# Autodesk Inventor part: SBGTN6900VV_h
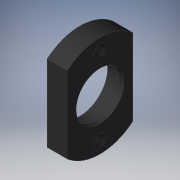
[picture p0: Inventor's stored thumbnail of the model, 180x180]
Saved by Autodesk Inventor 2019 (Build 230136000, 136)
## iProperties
Created: 2022-11
Part Number: SBGTN6900VV_h
Material: Generic
Catalog Web Link: www.cadenas.de
Description: BGTNB, BGTN, SBGTN_housing-Bearings with Housings - Space Saving, Small Flange - Non-Retained
Vendor: MISUMI
Document SubType Name: Modeling
Designer: psAdmin
Manufacturer: MISUMI
Mass: 4.62204 g
Surface Area: 29.706 cm^2
Volume: 4.62204 cm^3
Density: 1 g/cm^3
Appearance: PSOLRGB-175-175-175
Category: PARTsolutions
Company: MISUMI
Title: SBGTN6900VV
Author: Cadenas PARTsolutions
Comments: Bearings with Housings - Space Saving, Small Flange - Non-Retained
PSOL_IDENT_0: {$CADENAS_DATA/23d-libs/misumi/metric/12_bearing_holders/bgtnb/housing_bgtnb.prj},201 {VTYP=3D},{NB=
PSOL_IDENT_1: SBGTN6900VV_h},{LINA=SBGTN6900VV},{NN=BGTNB, BGTN, SBGTN_housing},{DATE=25.04.2017 02:57:07},{GEOMDA
PSOL_IDENT_2: TE=10.07.2015 02:20:10},{VERSION=},{LINEID=90},{WBVAR=MATB,ST,SEAL,ALT1},{WBNUMERIC=}  {NB=SBGTN6900
PSOL_IDENT_3: VV_h},{LINA=SBGTN6900VV},{KT=DUMMY},{PN=SBGTN6900VV},{TYPE=SBGTN},{MATB=SS},{MATBALG= 'S' , 'Steel'
PSOL_IDENT_4: , 'SS' , 'Stainless Steel' },{ST=-},{STALG= '-' , '-' },{BN=6900},{SEAL=VV},{SEALALG= 'ZZ' , 'Double
PSOL_IDENT_5: Shielded' , 'VV' , 'Non-Contact Sealed Rubber Seal' , 'DD' , 'Contact Sealed Rubber Seal' },{DD=10}
PSOL_IDENT_6: ,{D=22},{B=6},{H=40},{W=26},{T=8},{DDHH=19},{A=31},{F=0},{M=M5},{ALT1=},{M3D=5}
NB: SBGTN6900VV_h
NN: BGTNB, BGTN, SBGTN_housing
NT: Bearings with Housings - Space Saving, Small Flange - Non-Retained
NBSYN: $PN._h
LINA: SBGTN6900VV
CATALOG: Misumi
PN: SBGTN6900VV
MATB: Stainless Steel
ST: -
BN: 6900
SEAL: Non-Contact Sealed Rubber Seal
DD: 10
D: 22
B: 6
H: 40
W: 26
T: 8
DDHH: 19
A: 31
F: 0
M: M5
ALT1: Bearing and Retaining Ring Assembled
SUPPLIER: MISUMI
ARTICLENO: SBGTN6900VV_h
BOMINFO: SBGTN6900VV
CREATOR: CADENAS GmbH
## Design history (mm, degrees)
sketch "Sketch_1"
  geometry: L1 (-13, 15.199)-(-13, -15.199); L2 (13, -15.199)-(13, 15.199); A1 r 20 centre (0, 0) between (-13, -15.199) and (13, -15.199); A2 r 20 centre (0, 0) between (13, 15.199) and (-13, 15.199)
  constraints: 4 end point, 4 point on circle, 2 centre point
extrude "Extrusion1" join sketch "Sketch_1" stored distance "d0" = 8; taper "d1" = 0 deg
sketch "Sketch2"
  geometry: 1 further point
hole "Hole1" sketch "Sketch2" at (0, 0) diameter "d2" = 19; stored, may be unused: countersink angle "d6" = 90 deg, drill point angle "d8" = 0 deg; dims "d3" = 6, "d4" = 22, "d5" = 6, "d7" = 8
sketch "Sketch_11"
  geometry: L1 (4, -15.5)-(-4, -15.5); L2 (-4, -15.5)-(-4, -13); L3 (-4, -13)-(-3.567, -13.433); L4 (-3.567, -13.433)-(3.567, -13.433); L5 (3.567, -13.433)-(4, -13); L6 (4, -13)-(4, -15.5); L7 (4, -15.5)-(-4, -15.5)
  constraints: 14 end point
revolve "Revolution1" sketch "Sketch_11" stored, may be unused: angle "d9" = 360 deg
thread "Thread1" dims "d10" = 7.134, "d11" = 0
sketch "Sketch_9"
  geometry: L1 (4, 15.5)-(-4, 15.5); L2 (-4, 15.5)-(-4, 18); L3 (-4, 18)-(-3.567, 17.567); L4 (-3.567, 17.567)-(3.567, 17.567); L5 (3.567, 17.567)-(4, 18); L6 (4, 18)-(4, 15.5); L7 (4, 15.5)-(-4, 15.5)
  constraints: 14 end point
revolve "Revolution2" sketch "Sketch_9" stored, may be unused: angle "d12" = 360 deg
thread "Thread2" dims "d13" = 7.134, "d14" = 0
node "housing_to_dummy_XY"
node "housing_to_dummy_YZ"
node "housing_to_dummy_ZX"
node "housing_to_dummy_X"
node "housing_to_dummy_Y"
node "housing_to_dummy_Z"
node "housing_to_dummy_Center"
node "to_bearings_XY"
node "to_bearings_YZ"
node "to_bearings_ZX"
node "to_bearings_X"
node "to_bearings_Y"
node "to_bearings_Z"
node "to_bearings_Center"
body "Solid1"
other parameters: "d15" = 0
